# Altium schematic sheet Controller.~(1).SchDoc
size A
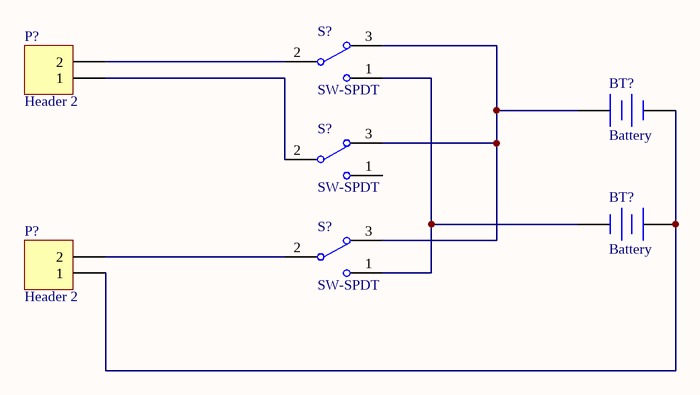
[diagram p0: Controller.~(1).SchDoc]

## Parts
(Parts that share a designator on the sheet are numbered #1, #2 ... from top to bottom, then left to right.)
BT?#1  Battery  [BAT-2]
BT?#2  Battery  [BAT-2]
P?#1  Header 2  [HDR1X2]
P?#2  Header 2  [HDR1X2]
S?#1  SW-SPDT  [TL36WW15050]
S?#2  SW-SPDT  [TL36WW15050]
S?#3  SW-SPDT  [TL36WW15050]

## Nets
NetBT?#1_1: BT?#1.1(+) S?#1.3 S?#2.3 S?#3.3
NetBT?#1_2: BT?#1.2(-) BT?#2.1(+) P?#2.1
NetBT?#2_2: BT?#2.2(-) S?#1.1 S?#3.1
NetP?#1_1: P?#1.1 S?#2.2
NetP?#1_2: P?#1.2 S?#1.2
NetP?#2_2: P?#2.2 S?#3.2

Not connected (* = marked no-connect by the designer): S?#2 1

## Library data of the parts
BT?#1 BT?#2 = Battery: Multicell Battery
P?#1 P?#2 = Header 2: Header, 2-Pin
S?#1-S?#3 = SW-SPDT: SPDT Subminiature Toggle Switch, Right Angle Mounting, Vertical Actuation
